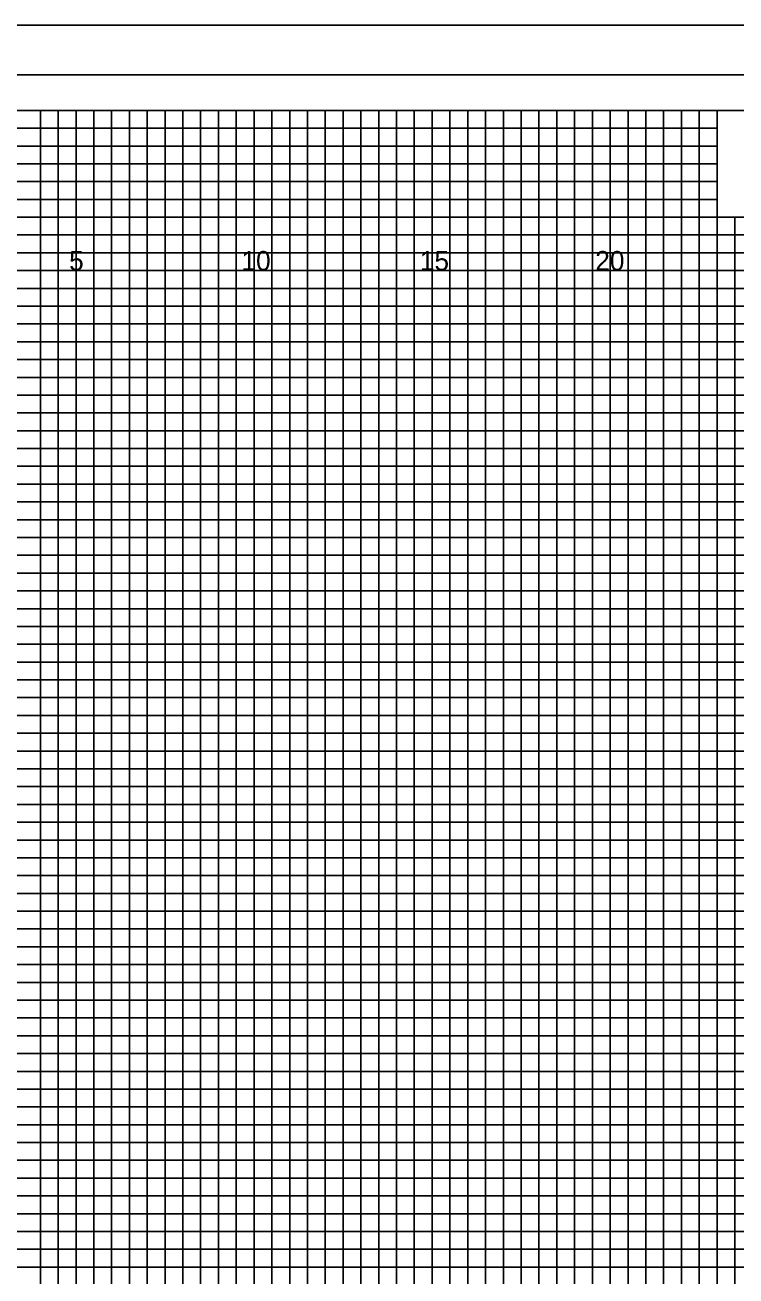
# Model space of a CAD drawing. Extents: x -4 to 103, y -2 to 6583.
# Drawn here: x 54.82 to 74.78, y 598.85 to 634 of the extents above; entities that cross this region are included whole.
import ezdxf

# ---------------------------------------------------------------- set-up
doc = ezdxf.new("R2010")
doc.units = 0
for name, color, linetype in [('Prop XS Offset Labels', 7, 'Continuous'), ('Sheet Cross Section CELL', 7, 'Continuous'), ('Sheet Cross Section Grid Major CELL', 7, 'Continuous'), ('Sheet Cross Section Grid Middle CELL', 7, 'Continuous'), ('Sheet Cutting Line CELL', 7, 'Continuous'), ('Sheet DOT Grid CELL', 7, 'Continuous'), ('Sheet Plot Border Inside CELL', 7, 'Continuous'), ('Sheet Plot Border Outside CELL', 7, 'Continuous')]:
    doc.layers.add(name, color=color, linetype=linetype)

msp = doc.modelspace()

# ---------------------------------------------------------------- linework, layer by layer
at = {"layer": 'Sheet Cross Section CELL'}
for points in [[(102.5, 631.6), (0, 631.6), (0, 566.6), (102.5, 566.6)], [(83.75, 631.6), (74.25, 631.6), (74.25, 628.6), (83.75, 628.6)]]:
    msp.add_lwpolyline(points, close=True, dxfattribs=at)
at = {"layer": 'Sheet Cross Section Grid Major CELL'}
for points in [[(56.25, 566.6), (56.25, 631.6), (58.75, 631.6), (58.75, 566.6)], [(61.25, 566.6), (61.25, 631.6), (63.75, 631.6), (63.75, 566.6)], [(66.25, 566.6), (66.25, 631.6), (68.75, 631.6), (68.75, 566.6)], [(71.25, 566.6), (71.25, 631.6), (73.75, 631.6), (73.75, 566.6)], [(0, 629.1), (74.25, 629.1)], [(0, 624.1), (102.5, 624.1), (102.5, 626.6), (0, 626.6)], [(0, 619.1), (102.5, 619.1), (102.5, 621.6), (0, 621.6)], [(0, 614.1), (102.5, 614.1), (102.5, 616.6), (0, 616.6)], [(0, 609.1), (102.5, 609.1), (102.5, 611.6), (0, 611.6)], [(0, 604.1), (102.5, 604.1), (102.5, 606.6), (0, 606.6)], [(0, 599.1), (102.5, 599.1), (102.5, 601.6), (0, 601.6)]]:
    msp.add_lwpolyline(points, dxfattribs=at)
at = {"layer": 'Sheet Cross Section Grid Middle CELL'}
for points in [[(55.25, 566.6), (55.25, 631.6), (55.75, 631.6), (55.75, 566.6)], [(56.75, 566.6), (56.75, 631.6), (57.25, 631.6), (57.25, 566.6)], [(57.75, 566.6), (57.75, 631.6), (58.25, 631.6), (58.25, 566.6)], [(59.25, 566.6), (59.25, 631.6), (59.75, 631.6), (59.75, 566.6)], [(60.25, 566.6), (60.25, 631.6), (60.75, 631.6), (60.75, 566.6)], [(61.75, 566.6), (61.75, 631.6), (62.25, 631.6), (62.25, 566.6)], [(62.75, 566.6), (62.75, 631.6), (63.25, 631.6), (63.25, 566.6)], [(64.25, 566.6), (64.25, 631.6), (64.75, 631.6), (64.75, 566.6)], [(65.25, 566.6), (65.25, 631.6), (65.75, 631.6), (65.75, 566.6)], [(66.75, 566.6), (66.75, 631.6), (67.25, 631.6), (67.25, 566.6)], [(67.75, 566.6), (67.75, 631.6), (68.25, 631.6), (68.25, 566.6)], [(69.25, 566.6), (69.25, 631.6)], [(69.25, 631.6), (69.75, 631.6), (69.75, 566.6)], [(70.25, 566.6), (70.25, 631.6), (70.75, 631.6), (70.75, 566.6)], [(71.75, 566.6), (71.75, 631.6), (72.25, 631.6), (72.25, 566.6)], [(72.75, 566.6), (72.75, 631.6), (73.25, 631.6), (73.25, 566.6)], [(0, 628.6), (0, 629.6), (74.25, 629.6), (74.25, 630.1), (0, 630.1), (0, 630.6), (74.25, 630.6), (74.25, 631.1), (0, 631.1)], [(0, 628.1), (102.5, 628.1), (102.5, 628.6), (0, 628.6)], [(74.25, 566.6), (74.25, 628.6), (74.75, 628.6), (74.75, 566.6)], [(0, 627.1), (102.5, 627.1), (102.5, 627.6), (0, 627.6)], [(0, 625.6), (102.5, 625.6), (102.5, 626.1), (0, 626.1)], [(0, 624.6), (102.5, 624.6), (102.5, 625.1), (0, 625.1)], [(0, 623.1), (102.5, 623.1), (102.5, 623.6), (0, 623.6)], [(0, 622.1), (102.5, 622.1), (102.5, 622.6), (0, 622.6)], [(0, 620.6), (102.5, 620.6), (102.5, 621.1), (0, 621.1)], [(0, 619.6), (102.5, 619.6), (102.5, 620.1), (0, 620.1)], [(0, 618.1), (102.5, 618.1), (102.5, 618.6), (0, 618.6)], [(0, 617.1), (102.5, 617.1), (102.5, 617.6), (0, 617.6)], [(0, 615.6), (102.5, 615.6), (102.5, 616.1), (0, 616.1)], [(0, 614.6), (102.5, 614.6), (102.5, 615.1), (0, 615.1)], [(0, 613.1), (102.5, 613.1), (102.5, 613.6), (0, 613.6)], [(0, 612.1), (102.5, 612.1), (102.5, 612.6), (0, 612.6)], [(0, 610.6), (102.5, 610.6), (102.5, 611.1), (0, 611.1)], [(0, 609.6), (102.5, 609.6), (102.5, 610.1), (0, 610.1)], [(0, 608.1), (102.5, 608.1), (102.5, 608.6), (0, 608.6)], [(0, 607.1), (102.5, 607.1), (102.5, 607.6), (0, 607.6)], [(0, 605.6), (102.5, 605.6), (102.5, 606.1), (0, 606.1)], [(0, 604.6), (102.5, 604.6), (102.5, 605.1), (0, 605.1)], [(0, 603.1), (102.5, 603.1), (102.5, 603.6), (0, 603.6)], [(0, 602.1), (102.5, 602.1), (102.5, 602.6), (0, 602.6)], [(0, 600.6), (102.5, 600.6), (102.5, 601.1), (0, 601.1)], [(0, 599.6), (102.5, 599.6), (102.5, 600.1), (0, 600.1)]]:
    msp.add_lwpolyline(points, dxfattribs=at)
at = {"layer": 'Sheet Cutting Line CELL'}
msp.add_line((-3.5, 634), (103.4, 634), dxfattribs=at)
at = {"layer": 'Sheet DOT Grid CELL'}
for p, q in [((56.25, 566.6), (56.25, 631.6)), ((58.75, 566.6), (58.75, 631.6)), ((61.25, 566.6), (61.25, 631.6)), ((63.75, 566.6), (63.75, 631.6)), ((66.25, 566.6), (66.25, 631.6)), ((68.75, 566.6), (68.75, 631.6)), ((71.25, 566.6), (71.25, 631.6)), ((73.75, 566.6), (73.75, 631.6)), ((0, 629.1), (74.25, 629.1)), ((0, 626.6), (102.5, 626.6)), ((0, 624.1), (102.5, 624.1)), ((0, 621.6), (102.5, 621.6)), ((0, 619.1), (102.5, 619.1)), ((0, 616.6), (102.5, 616.6)), ((0, 614.1), (102.5, 614.1)), ((0, 611.6), (102.5, 611.6)), ((0, 609.1), (102.5, 609.1)), ((0, 606.6), (102.5, 606.6)), ((0, 604.1), (102.5, 604.1)), ((0, 601.6), (102.5, 601.6)), ((0, 599.1), (102.5, 599.1))]:
    msp.add_line(p, q, dxfattribs=at)
at = {"layer": 'Sheet Plot Border Inside CELL'}
msp.add_lwpolyline([(103, 632.6), (-2.8, 632.6), (-2.8, 565.6), (103, 565.6)], close=True, dxfattribs=at)
at = {"layer": 'Sheet Plot Border Outside CELL'}
msp.add_lwpolyline([(103.4, 634), (-3.5, 634), (-3.5, 564.175), (103.4, 564.175)], close=True, dxfattribs=at)

# ---------------------------------------------------------------- texts
at = {"layer": 'Prop XS Offset Labels'}
for s, p in [('5', (56.057, 627.1)), ('10', (60.897, 627.1)), ('15', (65.906, 627.1)), ('20', (70.831, 627.1))]:
    msp.add_text(s, height=0.55, dxfattribs=at).set_placement(p)

doc.saveas('drawing.dxf')
